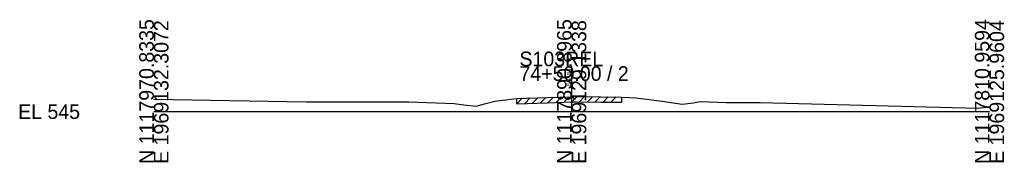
# Model space of a CAD drawing. Extents: x -26 to 163, y -10 to 24518.
# Drawn here: x -25.7 to 162.8, y 22990.3 to 23017.6 of the extents above; entities that cross this region are included whole.
import ezdxf

# ---------------------------------------------------------------- set-up
doc = ezdxf.new("R2010")
doc.units = 0
for name, color, linetype in [('RD_GPK_XS_Cell', 7, 'Continuous'), ('RD_XS_ExGround', 7, 'Continuous'), ('RD_XS_ExPaveRet', 7, 'Continuous'), ('RD_XS_TX_Elev_EX', 7, 'Continuous')]:
    doc.layers.add(name, color=color, linetype=linetype)

msp = doc.modelspace()

# ---------------------------------------------------------------- linework, layer by layer
at = {"layer": 'RD_GPK_XS_Cell'}
for p, q in [((80, 23000), (80, 23008.68)), ((0, 23000), (80, 23000)), ((80, 23000), (160, 23000))]:
    msp.add_line(p, q, dxfattribs=at)
at = {"layer": 'RD_XS_ExGround'}
msp.add_lwpolyline([(0, 23002.4), (29.19, 23001.9), (48.81, 23001.84), (57.48, 23001.53), (59.34, 23001.28), (61.69, 23001.05), (63.31, 23001.49), (65.3, 23001.97), (67.35, 23002.24), (69.5, 23002.52), (75.35, 23002.71), (80, 23002.86), (80.93, 23002.89), (85.61, 23002.83), (89.55, 23002.79), (91.07, 23002.71), (92.31, 23002.65), (97.3, 23001.97), (101.14, 23001.43), (103.3, 23001.71), (104.61, 23001.94), (109.6, 23001.74), (116.08, 23001.72), (157.76, 23000.67), (160, 23000.91)], dxfattribs=at)
at = {"layer": 'RD_XS_ExPaveRet'}
for p, q in [((80, 23001.86), (81.02, 23002.89)), ((81.5, 23001.88), (82.48, 23002.87)), ((69.5, 23001.52), (70.53, 23002.56)), ((69.5, 23001.52), (69.5, 23002.52)), ((69.5, 23001.52), (75.35, 23001.71)), ((71, 23001.57), (72.03, 23002.61)), ((72.5, 23001.62), (73.53, 23002.65)), ((74, 23001.67), (75.03, 23002.7)), ((75.35, 23001.71), (80, 23001.86)), ((75.5, 23001.72), (76.53, 23002.75)), ((77, 23001.76), (78.03, 23002.8)), ((78.5, 23001.81), (79.53, 23002.85)), ((80, 23001.86), (80.93, 23001.89)), ((80.93, 23001.89), (85.61, 23001.83)), ((83, 23001.86), (83.98, 23002.85)), ((84.5, 23001.84), (85.48, 23002.83)), ((85.61, 23001.83), (89.55, 23001.79)), ((86, 23001.82), (86.99, 23002.82)), ((87.5, 23001.81), (88.49, 23002.8)), ((89.55, 23002.79), (89.55, 23001.79))]:
    msp.add_line(p, q, dxfattribs=at)

# ---------------------------------------------------------------- texts
at = {"layer": 'RD_GPK_XS_Cell'}
for s, p in [('N 1117970.8335', (0, 22990)), ('E 1969132.3072', (2.8, 22990)), ('N 1117890.8965', (80, 22990)), ('E 1969129.1338', (82.8, 22990)), ('N 1117810.9594', (160, 22990)), ('E 1969125.9604', (162.8, 22990))]:
    msp.add_text(s, height=2.8, rotation=90, dxfattribs=at).set_placement(p)
for s, p in [('S103REL', (70, 23008.68)), ('74+50.00 / 2', (70, 23005.88)), ('EL 545', (-26, 22998.6))]:
    msp.add_text(s, height=2.8, dxfattribs=at).set_placement(p)
at = {"layer": 'RD_XS_TX_Elev_EX'}
msp.add_text('547.86', height=0.8, rotation=90, dxfattribs=at).set_placement((79.9, 23004.86))

doc.saveas('drawing.dxf')
